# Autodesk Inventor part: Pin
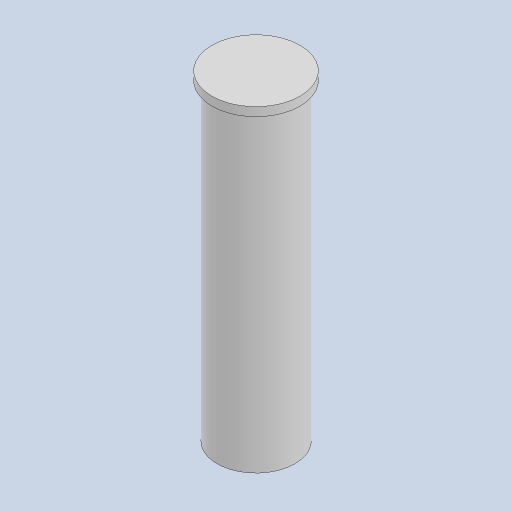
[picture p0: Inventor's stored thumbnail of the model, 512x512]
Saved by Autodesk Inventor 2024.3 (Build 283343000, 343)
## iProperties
Created: 2025-10
Part Number: Pin
Material: Genérico
Document SubType Name: Modeling
Designer: Asus
Density: 1 g/cm^3
Appearance: Valor por defecto
Author: Asus
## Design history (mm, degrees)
sketch "Boceto1"
  geometry: C1 r 25.4 at (0, 0); 1 further point
  constraints: 1 centre point, 1 coincident
  dimensions: "d0" = 50.8 diameter of C1
extrude "Extrusión1" new body sketch "Boceto1" distance "d1" = 5; taper "d2" = 0 deg
sketch "Boceto2"
  geometry: C1 r 22.5 at (0, 0); 1 further point
  constraints: 1 centre point, 1 coincident
  dimensions: "d3" = 45 diameter of C1
extrude "Extrusión2" join sketch "Boceto2" distance "d4" = 180; taper "d5" = 0 deg
sketch "Boceto3"
  geometry: 2 further points
  constraints: 1 coincident
hole "Agujero1" sketch "Boceto3" at (0, 0) diameter "d6" = 16.3068; stored, may be unused: countersink angle "d10" = 90 deg, drill point angle "d12" = 118 deg; dims "d7" = 38.1, "d8" = 4, "d9" = 2, "d11" = 20
node "Sólido1"
